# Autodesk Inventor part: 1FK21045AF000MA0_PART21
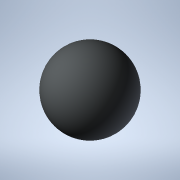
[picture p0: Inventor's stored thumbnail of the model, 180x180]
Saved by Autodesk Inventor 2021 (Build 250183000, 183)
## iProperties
Created: 2025-04
Part Number: 1FK21045AF000MA0_PART21
Material: Generic
Catalog Web Link: www.3dfindit.com
Description: -Servo synchronous motor
Document SubType Name: Modeling
Designer: psAdmin
Mass: 0.137258 g
Surface Area: 1.2868 cm^2
Volume: 0.137258 cm^3
Density: 1 g/cm^3
Appearance: PSOLRGB-212-217-219
Category: PARTsolutions
Title: 1FK21045AF000MA0_PART21
Author: Cadenas PARTsolutions
Comments: Servo synchronous motor
Sending System: PARTsolutions
Preprocessor: ST-DEVELOPER v19.3
PSOL_IDENT_0: {$CADENAS_DATA/23d-libs/siemens_ag/_cat_/8b/0a/1fk21045af000ma0.prj},216 {VTYP=3D},{NB=1FK21045AF000
PSOL_IDENT_1: MA0_PART21},{LINA=1FK21045AF000MA0_PART21},{NN=1FK21045AF000MA0_PART21},{NOPRJ=TRUE},{DATE=19.08.202
PSOL_IDENT_2: 5 14:00:48},{GEOMDATE=30.07.2025 02:00:28},{VERSION=},{LINEID=10},{WBVAR=},{WBNUMERIC=}  {NB=1FK2104
PSOL_IDENT_3: 5AF000MA0_PART21},{LINA=1FK21045AF000MA0_PART21},{KT=DUMMY},{PREVIEW=../../../_pool_/a9/69/p_d211_xx
PSOL_IDENT_4: _00818j.png},{DESCSHORT=SIMOTICS S-1FK2 HD, SINAMICS S210 3AC 400V-480V, 2.4 Nm, 3000 rpm},{DESCLONG=
PSOL_IDENT_5: SIMOTICS S-1FK2 HD servo motor M0=2.4 Nm; PN = 0.75 kW at nN=3000 rpm (380-480 V); PN = 0.375 kW at
PSOL_IDENT_6: nN=1500 rpm (200-240 V); degree of protection IP64; cylindrical shaft D19x40mm; absolute encoder 22-
PSOL_IDENT_7: bit + 12-bit multiturn (encoder AM22DQC); with OCC interface; plug size M17, rotatable; SIMOTICS S-1
PSOL_IDENT_8: FK2 servomotorfor a wide range of uses in industrial environments. SIMOTICS S‑1FK2 servomotors are c
PSOL_IDENT_9: ompact synchronous motors with a high dynamic performance that set themselves apart as a result of t
PSOL_IDENT_10: heir high power density, degree of protection and overload capability. The motors are available in t
PSOL_IDENT_11: wo variants: as High Dynamic variant (highest dynamic performance as a result of the low intrinsic m
PSOL_IDENT_12: oment of inertia for applications demanding a high dynamic performance with low moved masses) - and
PSOL_IDENT_13: as Compact variant (precise and stable closed-loop control for medium up to large moved masses as a
PSOL_IDENT_14: result of a medium intrinsic moment of inertia). SIMOTICSS‑1FK2 servomotors fully exploit their stre
PSOL_IDENT_15: ngths in a system with the SINAMICSS210 frequency converter and simple connection using the one cabl
PSOL_IDENT_16: e connection (OCC). Advantages include the short control and positioning times, fast and precise cor
PSOL_IDENT_17: rection of disturbing quantities as well as stable control with a high dynamic performance. The serv
PSOL_IDENT_18: o motors can be configured to address a wide range of requirements. For example with and without hol
PSOL_IDENT_19: ding brake, IP64 or IP65 degree of protection, singleturn or multiturn absolute encoders - to name j
PSOL_IDENT_20: ust a few. Further, the servomotors are available in different shaft heights extending from 20 to 10
PSOL_IDENT_21: 0. A shaft sealing ring is available to achieve an IP65 degree of protection and for subsequent moun
PSOL_IDENT_22: ting at the motor or as spare part. SIMOTICS - the optimum motor for each and every motion control a
PSOL_IDENT_23: pplication.},{INTNO=195125050112},{SUPPLIERALTNO=1FK2104-5AF00-0MA0},{MANUID=1FK21045AF000MA0},{MANU
PSOL_IDENT_24: NAME=Siemens},{MANUTYPEDESC=Synchronous motor 1FK2-HD 2.4 NM},{AAU732=SIMOTICS},{AAO057=S-1FK2},{AAU
PSOL_IDENT_25: 734=SIMOTICS S-1FK2 HD servo motor M0=2.4 Nm; PN = 0.75 kW at nN=3000 rpm (380-480 V); PN = 0.375 kW
PSOL_IDENT_26: at nN=1500 rpm (200-240 V); degree of protection IP64; cylindrical shaft D19x40mm; absolute encoder
PSOL_IDENT_27: 22-bit + 12-bit multiturn (encoder AM22DQC); with OCC interface; plug size M17, rotatable;},{AAW338=
PSOL_IDENT_28: Synchronous motor 1FK2-HD 2.4 NM},{AAO742=SIMOTICS},{AAO663=4042948692912},{NOCUPEROU=1},{PRICEQUANT
PSOL_IDENT_29: ITY=1},{QUANTITYMIN=1},{QUANTITYINT=1},{CTN=85015100},{COO=DE},{AAO676=1FK2104-5AF00-0MA0},{AAO677=S
PSOL_IDENT_30: iemens AG},{ORDERUNIT=C62},{CONTENTUNIT=C62}
NB: 1FK21045AF000MA0_PART21
NT: Servo synchronous motor
NBSYN: $MANUID._PART21
LINA: 1FK21045AF000MA0_PART21
CATALOG: SIEMENS
PREVIEW: ../../../_pool_/a9/69/p_d211_xx_00818j.png
DESCSHORT: SIMOTICS S-1FK2 HD, SINAMICS S210 3AC 400V-480V, 2.4 Nm, 3000 rpm
DESCLONG: SIMOTICS S-1FK2 HD servo motor M0=2.4 Nm; PN = 0.75 kW at nN=3000 rpm (380-480 V); PN = 0.375 kW at nN=1500 rpm (200-240 V); degree of protection IP64; cylindri
INTNO: 195125050112
SUPPLIERALTNO: 1FK2104-5AF00-0MA0
MANUID: 1FK21045AF000MA0
MANUNAME: Siemens
MANUTYPEDESC: Synchronous motor 1FK2-HD 2.4 NM
AAU732: SIMOTICS
AAO057: S-1FK2
AAU734: SIMOTICS S-1FK2 HD servo motor M0=2.4 Nm; PN = 0.75 kW at nN=3000 rpm (380-480 V); PN = 0.375 kW at nN=1500 rpm (200-240 V); degree of protection IP64; cylindri
AAW338: Synchronous motor 1FK2-HD 2.4 NM
AAO742: SIMOTICS
AAO663: 4042948692912.0
NOCUPEROU: 1
PRICEQUANTITY: 1
QUANTITYMIN: 1
QUANTITYINT: 1
CTN: 85015100
COO: DE
ARTICLENO: 1FK21045AF000MA0_PART21
BOMINFO: 1FK21045AF000MA0_PART21
CREATOR: CADENAS GmbH
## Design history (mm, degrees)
feature "2025_04_17_15_40_42_0766"
body "Solid1"
